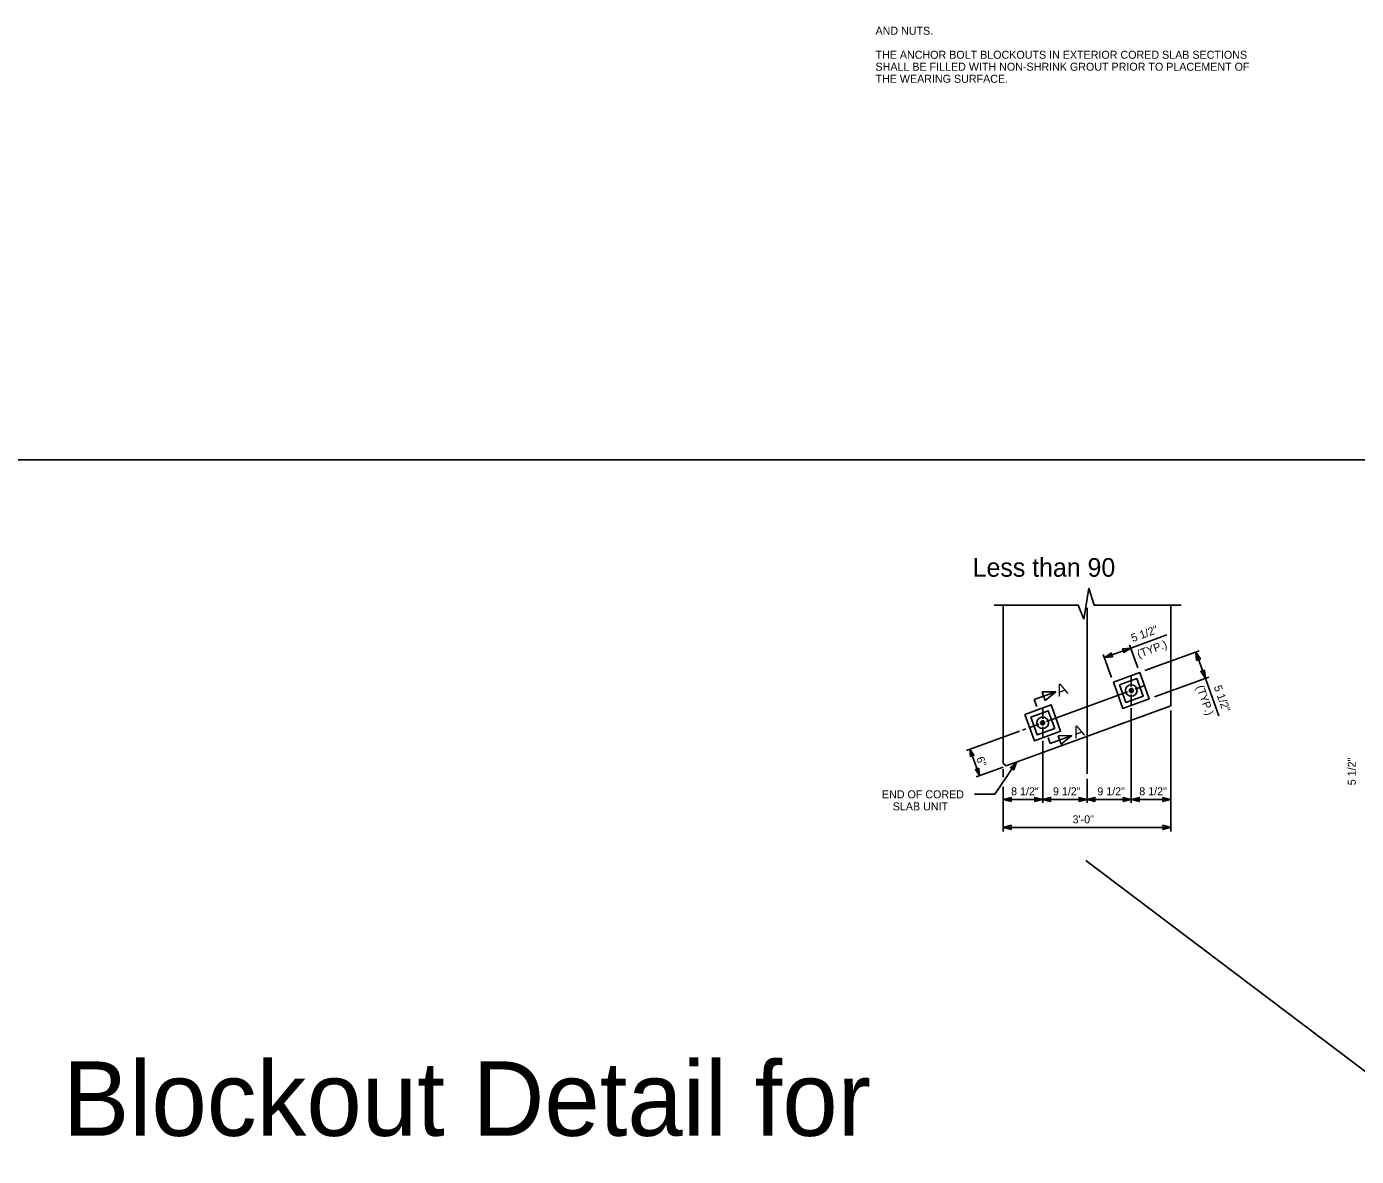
# Model space of a CAD drawing. Extents: x 0 to 177, y -1 to 127.
# Drawn here: x 30 to 53.76, y 57.55 to 77.74 of the extents above; entities that cross this region are included whole.
import ezdxf

# ---------------------------------------------------------------- set-up
doc = ezdxf.new("R2010")
doc.units = 0
for name, color, linetype in [('Arrowhead Terminators CELL', 7, 'Continuous'), ('Default', 7, 'Continuous'), ('Dimension Lines', 7, 'Continuous'), ('Mis Center Lines', 7, 'Continuous'), ('Plan Sheet', 7, 'Continuous'), ('Rebar Lines', 7, 'Continuous'), ('Structural Steel Lines', 7, 'Continuous'), ('Subtitle Text', 7, 'Continuous'), ('Sup Concrete Girder Lines', 7, 'Continuous'), ('Sup Cored Slab Unit', 7, 'Continuous'), ('Text', 7, 'Continuous'), ('User Information Notes', 7, 'Continuous')]:
    doc.layers.add(name, color=color, linetype=linetype)

msp = doc.modelspace()

# ---------------------------------------------------------------- linework, layer by layer
at = {"layer": 'Arrowhead Terminators CELL'}
for points in [[(49.26, 66.466), (49.382, 66.548), (49.406, 66.482)], [(49.73, 66.637), (49.608, 66.555), (49.584, 66.622)], [(50.892, 66.563), (50.975, 66.442), (50.908, 66.417)], [(51.064, 66.093), (50.981, 66.215), (51.048, 66.239)], [(48.203, 65.702), (48.391, 65.856), (48.148, 65.853)], [(48.433, 65.069), (48.676, 65.073), (48.488, 64.919)], [(47.689, 64.599), (47.64, 64.461), (47.581, 64.5)], [(47.449, 63.933), (47.591, 63.969), (47.591, 63.897)], [(48.157, 63.933), (48.014, 63.897), (48.014, 63.969)], [(48.157, 63.933), (48.299, 63.969), (48.299, 63.897)], [(48.949, 63.933), (48.806, 63.897), (48.806, 63.969)], [(48.949, 63.933), (49.091, 63.969), (49.091, 63.897)], [(49.74, 63.933), (49.598, 63.897), (49.598, 63.969)], [(49.74, 63.933), (49.883, 63.969), (49.883, 63.897)], [(50.449, 63.933), (50.306, 63.897), (50.306, 63.969)], [(47.449, 63.433), (47.591, 63.469), (47.591, 63.397)], [(50.449, 63.433), (50.306, 63.397), (50.306, 63.469)]]:
    msp.add_lwpolyline(points, close=True, dxfattribs=at)
at = {"layer": 'Default'}
for p, q in [((48.006, 65.716), (48.391, 65.856)), ((48.05, 65.595), (48.006, 65.716)), ((48.291, 64.933), (48.254, 65.036)), ((48.291, 64.933), (48.676, 65.073))]:
    msp.add_line(p, q, dxfattribs=at)
at = {"layer": 'Dimension Lines'}
for p, q in [((50.373, 66.871), (49.73, 66.637)), ((49.73, 66.637), (49.26, 66.466)), ((49.709, 66.694), (49.859, 66.283)), ((50.955, 66.586), (49.984, 66.233)), ((50.892, 66.563), (51.064, 66.093)), ((49.239, 66.523), (49.389, 66.112)), ((49.74, 66.137), (49.74, 65.949)), ((51.126, 66.116), (50.155, 65.763)), ((51.064, 66.093), (51.307, 65.425)), ((49.671, 65.853), (49.495, 65.788)), ((49.985, 65.967), (49.809, 65.902)), ((49.74, 65.806), (49.74, 65.618)), ((48.157, 65.56), (48.157, 65.373)), ((48.402, 65.39), (48.226, 65.326)), ((49.74, 65.562), (49.74, 63.872)), ((50.449, 65.519), (50.449, 63.361)), ((47.744, 65.151), (46.797, 64.806)), ((47.853, 65.191), (47.795, 65.169)), ((48.088, 65.276), (47.912, 65.212)), ((48.157, 65.23), (48.157, 65.042)), ((48.157, 64.98), (48.157, 63.872)), ((46.856, 64.828), (47.027, 64.358)), ((47.449, 64.511), (46.968, 64.337)), ((47.689, 64.599), (47.304, 64.024)), ((47.449, 64.47), (47.449, 64.328)), ((48.949, 64.298), (48.949, 63.872)), ((47.304, 64.024), (46.936, 64.024)), ((47.449, 64.157), (47.449, 63.361)), ((48.157, 63.933), (47.449, 63.933)), ((48.949, 63.933), (48.157, 63.933)), ((49.74, 63.933), (48.949, 63.933)), ((50.449, 63.933), (49.74, 63.933)), ((50.449, 63.433), (47.449, 63.433))]:
    msp.add_line(p, q, dxfattribs=at)
for points in [[(49.711, 65.867), (49.74, 65.878), (49.74, 65.846)], [(49.77, 65.888), (49.74, 65.878), (49.74, 65.909)], [(48.127, 65.291), (48.157, 65.301), (48.157, 65.27)], [(48.187, 65.312), (48.157, 65.301), (48.157, 65.333)], [(46.898, 64.71), (46.904, 64.712), (46.856, 64.828), (46.91, 64.715), (46.916, 64.717), (46.856, 64.828), (46.922, 64.719), (46.928, 64.721), (46.856, 64.828), (46.869, 64.7), (46.875, 64.702), (46.856, 64.828), (46.881, 64.704), (46.887, 64.706), (46.856, 64.828), (46.893, 64.708), (46.928, 64.721), (46.869, 64.7), (46.856, 64.828), (46.928, 64.721)], [(46.984, 64.475), (46.99, 64.477), (47.027, 64.358), (46.996, 64.48), (47.001, 64.482), (47.027, 64.358), (47.007, 64.484), (47.013, 64.486), (47.027, 64.358), (46.955, 64.465), (46.96, 64.467), (47.027, 64.358), (46.966, 64.469), (46.972, 64.471), (47.027, 64.358), (46.978, 64.473), (47.013, 64.486), (46.955, 64.465), (47.027, 64.358), (47.013, 64.486)]]:
    msp.add_lwpolyline(points, dxfattribs=at)
at = {"layer": 'Mis Center Lines'}
for p, q in [((48.949, 67.355), (48.949, 64.389)), ((48.402, 65.39), (49.495, 65.788))]:
    msp.add_line(p, q, dxfattribs=at)
at = {"layer": 'Plan Sheet'}
msp.add_line((0, 70), (79.481, 70), dxfattribs=at)
at = {"layer": 'Rebar Lines'}
for centre in [(49.74, 65.878), (48.157, 65.301)]:
    msp.add_circle(centre, 0.0365, dxfattribs=at)
at = {"layer": 'Structural Steel Lines'}
for points in [[(49.527, 65.977), (49.641, 65.664), (49.954, 65.778), (49.84, 66.091)], [(47.943, 65.401), (48.057, 65.088), (48.371, 65.202), (48.257, 65.515)]]:
    msp.add_lwpolyline(points, close=True, dxfattribs=at)
at = {"layer": 'Sup Concrete Girder Lines'}
for p, q in [((48.981, 67.704), (48.895, 67.15)), ((49.076, 67.405), (48.981, 67.704)), ((48.789, 67.405), (47.289, 67.405)), ((47.449, 64.574), (47.449, 67.405)), ((48.895, 67.15), (48.789, 67.405)), ((50.63, 67.405), (49.076, 67.405)), ((50.449, 65.603), (50.449, 67.405)), ((50.449, 65.603), (47.507, 64.533)), ((47.449, 64.574), (47.507, 64.533))]:
    msp.add_line(p, q, dxfattribs=at)
for centre in [(49.74, 65.878), (48.157, 65.301)]:
    msp.add_circle(centre, 0.104, dxfattribs=at)
at = {"layer": 'Sup Cored Slab Unit'}
for points in [[(49.42, 66.027), (49.591, 65.557), (50.061, 65.728), (49.89, 66.198)], [(47.836, 65.451), (48.008, 64.981), (48.477, 65.152), (48.306, 65.622)]]:
    msp.add_lwpolyline(points, close=True, dxfattribs=at)
at = {"layer": 'Text'}
for p, q in [((50.449, 65.675), (50.449, 67.124)), ((50.449, 65.675), (50.449, 66.807)), ((50.449, 65.675), (50.449, 66.672)), ((50.449, 65.675), (50.449, 66.584)), ((50.449, 65.675), (50.449, 66.377)), ((49.985, 65.434), (49.892, 65.4)), ((49.609, 65.298), (49.396, 65.22))]:
    msp.add_line(p, q, dxfattribs=at)
at = {"layer": 'User Information Notes'}
for q in [(48.93, 62.839), (55.93, 57.553)]:
    msp.add_line((48.93, 62.839), q, dxfattribs=at)

# ---------------------------------------------------------------- texts
at = {"layer": 'Default'}
for p in [(48.441, 65.764), (48.74, 65.015)]:
    msp.add_text('A', height=0.215, rotation=20.0008, dxfattribs=at).set_placement(p)
at = {"layer": 'Subtitle Text'}
for s, p in [('AND NUTS.', (45.169, 77.595)), ('THE ANCHOR BOLT BLOCKOUTS IN EXTERIOR CORED SLAB SECTIONS ', (45.169, 77.166)), ('SHALL BE FILLED WITH NON-SHRINK GROUT PRIOR TO PLACEMENT OF ', (45.169, 76.952)), ('THE WEARING SURFACE.', (45.169, 76.737))]:
    msp.add_text(s, height=0.143, dxfattribs=at).set_placement(p)
at = {"layer": 'Text'}
for s, rotation, p in [('5 1/2"', 20.0008, (49.768, 66.742)), ('(TYP.)', 20.0008, (49.874, 66.457)), ('(TYP.)', 290.0008, (50.896, 65.941)), ('5 1/2"', 290.0008, (51.212, 65.942)), ('6"', 290.0121, (46.965, 64.666)), ('5 1/2"', 90, (53.752, 64.185))]:
    msp.add_text(s, height=0.143, rotation=rotation, dxfattribs=at).set_placement(p)
for s, height, p in [('END OF CORED', 0.143, (45.284, 63.951)), ('8 1/2"', 0.143, (47.592, 64.005)), ('9 1/2"', 0.143, (48.341, 64.005)), ('9 1/2"', 0.143, (49.133, 64.005)), ('8 1/2"', 0.143, (49.883, 64.005)), ('SLAB UNIT', 0.143, (45.477, 63.736)), ('3\'-0"', 0.143, (48.691, 63.505)), ('Blockout Detail for', 1.33067, (30.647, 57.921))]:
    msp.add_text(s, height=height, dxfattribs=at).set_placement(p)
at = {"layer": 'User Information Notes'}
msp.add_text('Less than 90', height=0.33267, dxfattribs=at).set_placement((46.906, 67.911))

doc.saveas('drawing.dxf')
